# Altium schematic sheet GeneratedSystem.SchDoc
size 244 x 96 mm
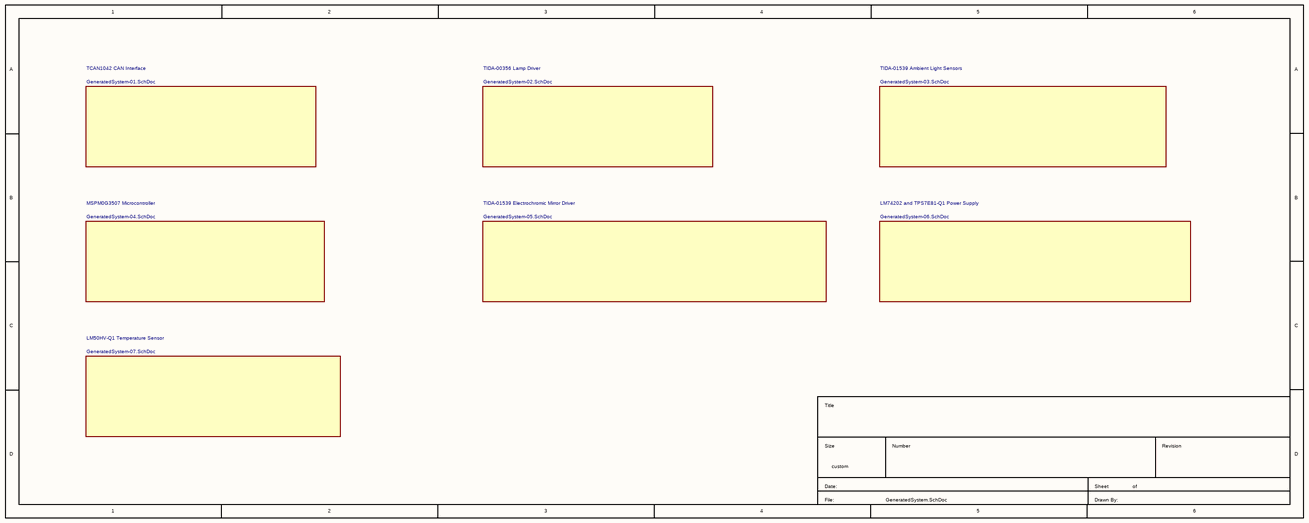
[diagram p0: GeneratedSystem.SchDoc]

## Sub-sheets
LM50HV-Q1 Temperature Sensor = GeneratedSystem-07.SchDoc: no entries
LM74202 and TPS7E81-Q1 Power Supply = GeneratedSystem-06.SchDoc: no entries
MSPM0G3507 Microcontroller = GeneratedSystem-04.SchDoc: no entries
TCAN1042 CAN Interface = GeneratedSystem-01.SchDoc: no entries
TIDA-00356 Lamp Driver = GeneratedSystem-02.SchDoc: no entries
TIDA-01539 Ambient Light Sensors = GeneratedSystem-03.SchDoc: no entries
TIDA-01539 Electrochromic Mirror Driver = GeneratedSystem-05.SchDoc: no entries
